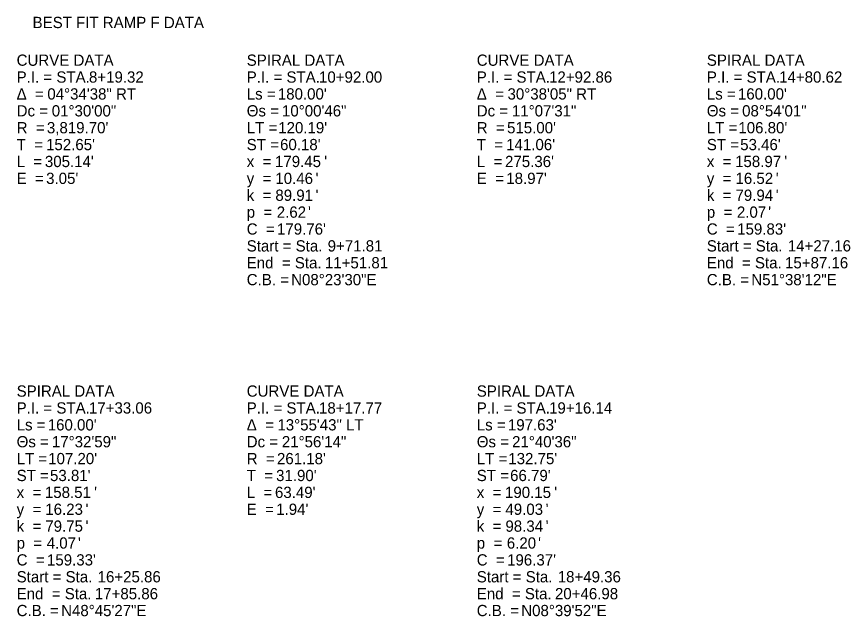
# Model space of a CAD drawing. Extents: x 1504629 to 1506299, y 325931 to 328016.
# Drawn here: x 1506091.9 to 1506299.4, y 326769.6 to 326918.8 of the extents above; entities that cross this region are included whole.
import ezdxf

# ---------------------------------------------------------------- set-up
doc = ezdxf.new("R2010")
doc.units = 0
doc.layers.add('GE_X_Alignment_100_Curve_Data', color=7, linetype='Continuous')
doc.layers.add('SC_Scratch1', color=7, linetype='Continuous')

msp = doc.modelspace()

# ---------------------------------------------------------------- texts
at = {"layer": 'GE_X_Alignment_100_Curve_Data'}
for s, p in [('CURVE DATA', (1506091.91, 326906.54)), ('SPIRAL DATA', (1506149.16, 326906.54)), ('CURVE DATA', (1506206.4, 326906.54)), ('SPIRAL DATA', (1506263.65, 326906.54)), ('P.I. = STA. ', (1506091.91, 326902.34)), ('8+19.32', (1506109.9, 326902.34)), ('P.I. = STA. ', (1506149.16, 326902.34)), ('10+92.00', (1506167.15, 326902.34)), ('P.I. = STA. ', (1506206.4, 326902.34)), ('12+92.86', (1506224.39, 326902.34)), ('P.I. = STA. ', (1506263.65, 326902.34)), ('14+80.62', (1506281.64, 326902.34)), ('Δ  = ', (1506091.91, 326898.14)), ('04°34\'38" RT', (1506099.55, 326898.14)), ('Ls = ', (1506149.16, 326898.14)), ("180.00'", (1506156.9, 326898.14)), ('Δ  = ', (1506206.4, 326898.14)), ('30°38\'05" RT', (1506214.05, 326898.14)), ('Ls = ', (1506263.65, 326898.14)), ("160.00'", (1506271.39, 326898.14)), ('Dc = ', (1506091.91, 326893.94)), ('01°30\'00"', (1506100.65, 326893.94)), ('Θs = ', (1506149.16, 326893.94)), ('10°00\'46"', (1506157.94, 326893.94)), ('Dc = ', (1506206.4, 326893.94)), ('11°07\'31"', (1506215.15, 326893.94)), ('Θs = ', (1506263.65, 326893.94)), ('08°54\'01"', (1506272.43, 326893.94)), ('R  = ', (1506091.91, 326889.74)), ("3,819.70'", (1506099.44, 326889.74)), ('LT = ', (1506149.16, 326889.74)), ("120.19'", (1506157, 326889.74)), ('R  = ', (1506206.4, 326889.74)), ("515.00'", (1506213.94, 326889.74)), ('LT = ', (1506263.65, 326889.74)), ("106.80'", (1506271.5, 326889.74)), ('T  = ', (1506091.91, 326885.54)), ("152.65'", (1506099.23, 326885.54)), ('ST = ', (1506149.16, 326885.54)), ("60.18'", (1506157.46, 326885.54)), ('T  = ', (1506206.4, 326885.54)), ("141.06'", (1506213.72, 326885.54)), ('ST = ', (1506263.65, 326885.54)), ("53.46'", (1506271.95, 326885.54)), ('L  = ', (1506091.91, 326881.34)), ("305.14'", (1506098.94, 326881.34)), ('179.45', (1506156.19, 326881.34)), ("'", (1506168.44, 326881.34)), ('L  = ', (1506206.4, 326881.34)), ("275.36'", (1506213.44, 326881.34)), ('158.97', (1506270.68, 326881.34)), ("'", (1506282.93, 326881.34)), ('x  = ', (1506149.16, 326881.34)), ('x  = ', (1506263.65, 326881.34)), ('E  = ', (1506091.91, 326877.14)), ("3.05'", (1506099.25, 326877.14)), ('10.46', (1506156.29, 326877.14)), ("'", (1506166.3, 326877.14)), ('E  = ', (1506206.4, 326877.14)), ("18.97'", (1506213.75, 326877.14)), ('16.52', (1506270.78, 326877.14)), ("'", (1506280.8, 326877.14)), ('y  = ', (1506149.16, 326877.14)), ('y  = ', (1506263.65, 326877.14)), ('k  = ', (1506149.16, 326872.94)), ('89.91', (1506156.29, 326872.94)), ("'", (1506166.3, 326872.94)), ('k  = ', (1506263.65, 326872.94)), ('79.94', (1506270.78, 326872.94)), ("'", (1506280.8, 326872.94)), ('2.62', (1506156.64, 326868.74)), ("'", (1506164.42, 326868.74)), ('2.07', (1506271.13, 326868.74)), ("'", (1506278.91, 326868.74)), ('p  = ', (1506149.16, 326868.74)), ('p  = ', (1506263.65, 326868.74)), ('C  = ', (1506149.16, 326864.54)), ("179.76'", (1506156.7, 326864.54)), ('C  = ', (1506263.65, 326864.54)), ("159.83'", (1506271.2, 326864.54)), ('Start = Sta. ', (1506149.16, 326860.34)), ('9+71.81', (1506169.3, 326860.34)), ('Start = Sta. ', (1506263.65, 326860.34)), ('14+27.16', (1506283.8, 326860.34)), ('End  = Sta. ', (1506149.16, 326856.14)), ('11+51.81', (1506168.62, 326856.14)), ('End  = Sta. ', (1506263.65, 326856.14)), ('15+87.16', (1506283.11, 326856.14)), ('C.B. = ', (1506149.16, 326851.94)), ('N08°23\'30"E', (1506160.22, 326851.94)), ('C.B. = ', (1506263.65, 326851.94)), ('N51°38\'12"E', (1506274.72, 326851.94)), ('SPIRAL DATA', (1506091.91, 326824.22)), ('CURVE DATA', (1506149.16, 326824.22)), ('SPIRAL DATA', (1506206.4, 326824.22)), ('P.I. = STA. ', (1506091.91, 326820.02)), ('17+33.06', (1506109.9, 326820.02)), ('P.I. = STA. ', (1506149.16, 326820.02)), ('18+17.77', (1506167.15, 326820.02)), ('P.I. = STA. ', (1506206.4, 326820.02)), ('19+16.14', (1506224.39, 326820.02)), ('Ls = ', (1506091.91, 326815.82)), ("160.00'", (1506099.65, 326815.82)), ('Δ  = ', (1506149.16, 326815.82)), ('13°55\'43" LT', (1506156.8, 326815.82)), ('Ls = ', (1506206.4, 326815.82)), ("197.63'", (1506214.15, 326815.82)), ('Θs = ', (1506091.91, 326811.62)), ('17°32\'59"', (1506100.69, 326811.62)), ('Dc = ', (1506149.16, 326811.62)), ('21°56\'14"', (1506157.9, 326811.62)), ('Θs = ', (1506206.4, 326811.62)), ('21°40\'36"', (1506215.19, 326811.62)), ('LT = ', (1506091.91, 326807.42)), ("107.20'", (1506099.76, 326807.42)), ('R  = ', (1506149.16, 326807.42)), ("261.18'", (1506156.69, 326807.42)), ('LT = ', (1506206.4, 326807.42)), ("132.75'", (1506214.25, 326807.42)), ('ST = ', (1506091.91, 326803.22)), ("53.81'", (1506100.21, 326803.22)), ('T  = ', (1506149.16, 326803.22)), ("31.90'", (1506156.47, 326803.22)), ('ST = ', (1506206.4, 326803.22)), ("66.79'", (1506214.7, 326803.22)), ('x  = ', (1506091.91, 326799.02)), ('158.51', (1506098.94, 326799.02)), ("'", (1506111.19, 326799.02)), ('L  = ', (1506149.16, 326799.02)), ("63.49'", (1506156.19, 326799.02)), ('x  = ', (1506206.4, 326799.02)), ('190.15', (1506213.43, 326799.02)), ("'", (1506225.69, 326799.02)), ('y  = ', (1506091.91, 326794.82)), ('16.23', (1506099.04, 326794.82)), ("'", (1506109.06, 326794.82)), ('E  = ', (1506149.16, 326794.82)), ("1.94'", (1506156.5, 326794.82)), ('y  = ', (1506206.4, 326794.82)), ('49.03', (1506213.53, 326794.82)), ("'", (1506223.55, 326794.82)), ('k  = ', (1506091.91, 326790.62)), ('79.75', (1506099.04, 326790.62)), ("'", (1506109.06, 326790.62)), ('k  = ', (1506206.4, 326790.62)), ('98.34', (1506213.53, 326790.62)), ("'", (1506223.55, 326790.62)), ('p  = ', (1506091.91, 326786.42)), ('4.07', (1506099.39, 326786.42)), ("'", (1506107.17, 326786.42)), ('p  = ', (1506206.4, 326786.42)), ('6.20', (1506213.88, 326786.42)), ("'", (1506221.66, 326786.42)), ('C  = ', (1506091.91, 326782.22)), ("159.33'", (1506099.46, 326782.22)), ('C  = ', (1506206.4, 326782.22)), ("196.37'", (1506213.95, 326782.22)), ('Start = Sta. ', (1506091.91, 326778.02)), ('16+25.86', (1506112.06, 326778.02)), ('Start = Sta. ', (1506206.4, 326778.02)), ('18+49.36', (1506226.55, 326778.02)), ('End  = Sta. ', (1506091.91, 326773.82)), ('17+85.86', (1506111.37, 326773.82)), ('End  = Sta. ', (1506206.4, 326773.82)), ('20+46.98', (1506225.86, 326773.82)), ('C.B. = ', (1506091.91, 326769.62)), ('N48°45\'27"E', (1506102.98, 326769.62)), ('C.B. = ', (1506206.4, 326769.62)), ('N08°39\'52"E', (1506217.47, 326769.62))]:
    msp.add_text(s, height=2.8, dxfattribs=at).set_placement(p)
at = {"layer": 'SC_Scratch1'}
msp.add_text('BEST FIT RAMP F DATA', height=2.8, dxfattribs=at).set_placement((1506095.88, 326915.92))

doc.saveas('drawing.dxf')
